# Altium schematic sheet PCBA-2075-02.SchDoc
size Tabloid; Organization: Hebi Robotics; Address1: Suite 780; Address2: 5001 Baum Blvd; Address3: Pittsburgh, PA 15213; Address4: USA
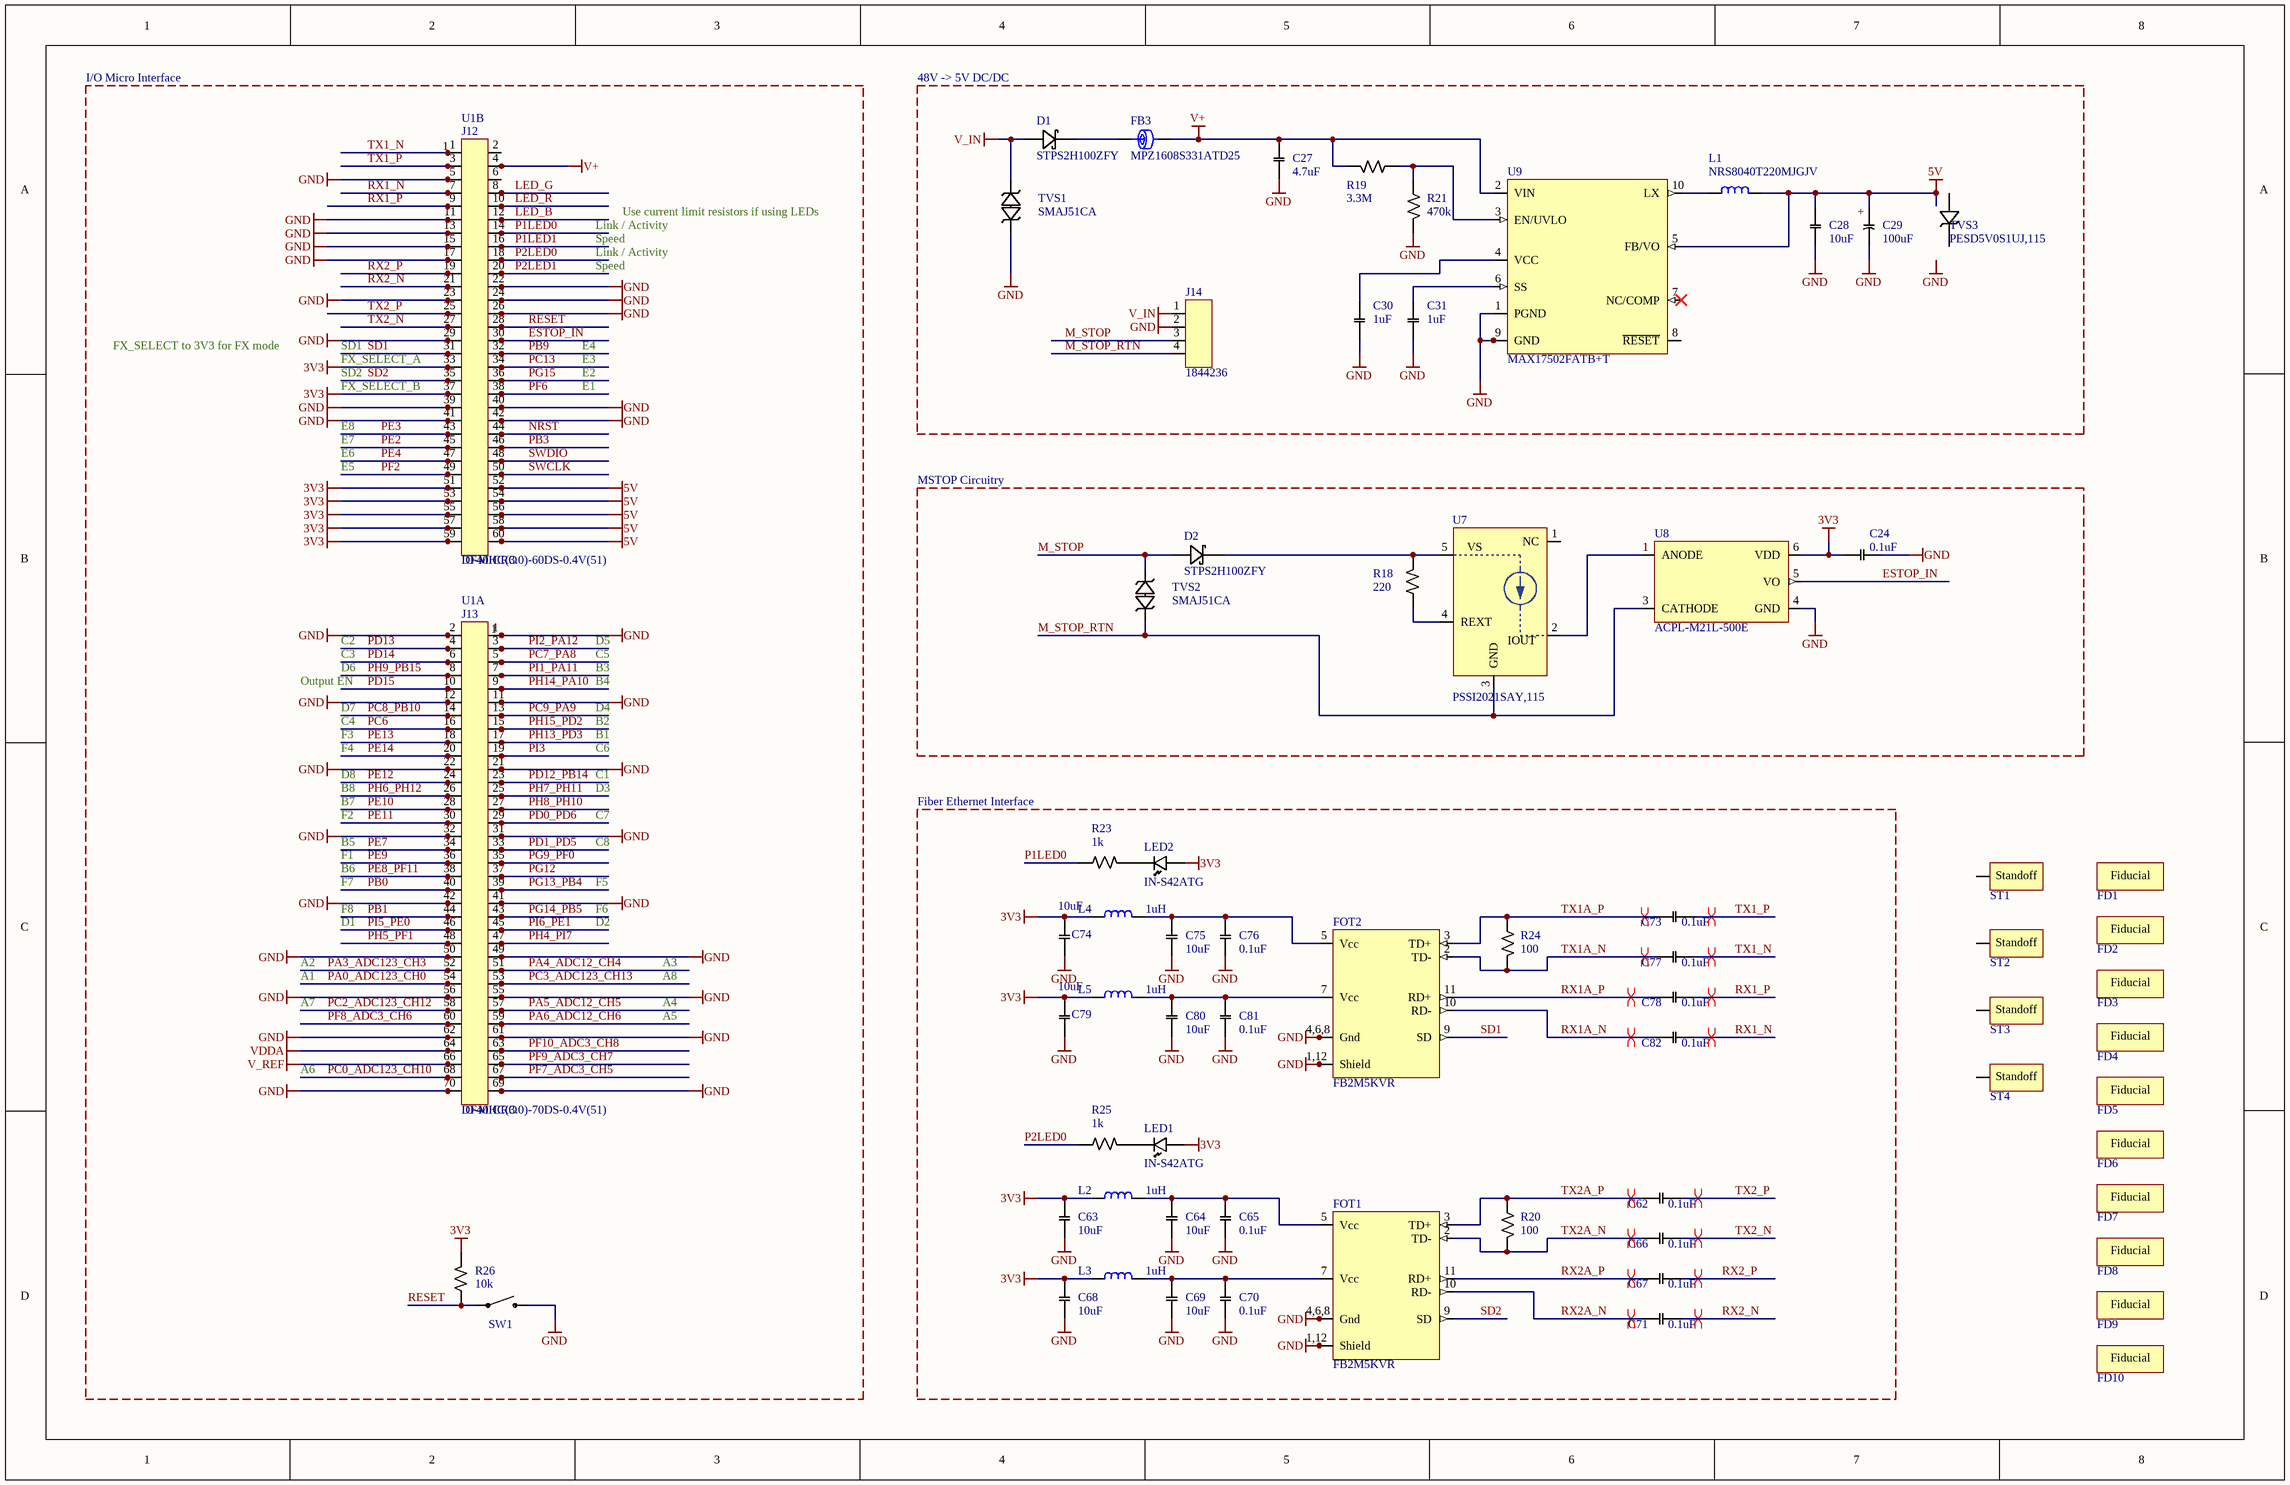
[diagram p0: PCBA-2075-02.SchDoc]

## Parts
C24  Capacitance: 0.1uF  [C0402]  (hidden comment: CMP-00040-11)
C27  Capacitance: 4.7uF  [C1210]  (hidden comment: C-4.7uf-X7S-100V-20%-1210)
C28  Capacitance: 10uF  [C0603]  (hidden comment: C-10uf-X5R-16V-10%-0603)
C29  Capacitance: 100uF  [CAPAE127P600-8N]  (hidden comment: 16SVPC100M)
C30  Capacitance: 1uF  [C0603]  (hidden comment: C-1uf-X7R-25V-10%-0603)
C31  Capacitance: 1uF  [C0603]  (hidden comment: C-1uf-X7R-25V-10%-0603)
C62  Capacitance: 0.1uF  [C0402]  (hidden comment: CMP-00040-11)
C63  Capacitance: 10uF  [C0603]  (hidden comment: C-10uf-X5R-16V-10%-0603)
C64  Capacitance: 10uF  [C0603]  (hidden comment: C-10uf-X5R-16V-10%-0603)
C65  Capacitance: 0.1uF  [C0402]  (hidden comment: CMP-00040-11)
C66  Capacitance: 0.1uF  [C0402]  (hidden comment: CMP-00040-11)
C67  Capacitance: 0.1uF  [C0402]  (hidden comment: CMP-00040-11)
C68  Capacitance: 10uF  [C0603]  (hidden comment: C-10uf-X5R-16V-10%-0603)
C69  Capacitance: 10uF  [C0603]  (hidden comment: C-10uf-X5R-16V-10%-0603)
C70  Capacitance: 0.1uF  [C0402]  (hidden comment: CMP-00040-11)
C71  Capacitance: 0.1uF  [C0402]  (hidden comment: CMP-00040-11)
C73  Capacitance: 0.1uF  [C0402]  (hidden comment: CMP-00040-11)
C74  Capacitance: 10uF  [C0603]  (hidden comment: C-10uf-X5R-16V-10%-0603)
C75  Capacitance: 10uF  [C0603]  (hidden comment: C-10uf-X5R-16V-10%-0603)
C76  Capacitance: 0.1uF  [C0402]  (hidden comment: CMP-00040-11)
C77  Capacitance: 0.1uF  [C0402]  (hidden comment: CMP-00040-11)
C78  Capacitance: 0.1uF  [C0402]  (hidden comment: CMP-00040-11)
C79  Capacitance: 10uF  [C0603]  (hidden comment: C-10uf-X5R-16V-10%-0603)
C80  Capacitance: 10uF  [C0603]  (hidden comment: C-10uf-X5R-16V-10%-0603)
C81  Capacitance: 0.1uF  [C0402]  (hidden comment: CMP-00040-11)
C82  Capacitance: 0.1uF  [C0402]  (hidden comment: CMP-00040-11)
D1  STPS2H100ZFY  [SOD123F_ST]
D2  STPS2H100ZFY  [SOD123F_ST]
FB3  MPZ1608S331ATD25  [FB0603]
FD1  FIDUCIAL  [fiducial_01]  (value not drawn)  (no BOM)
FD2  FIDUCIAL  [fiducial_01]  (value not drawn)  (no BOM)
FD3  FIDUCIAL  [fiducial_01]  (value not drawn)  (no BOM)
FD4  FIDUCIAL  [fiducial_01]  (value not drawn)  (no BOM)
FD5  *  [fiducial_01_no_overlay]  (value not drawn)  (no BOM)
FD6  *  [fiducial_01_no_overlay]  (value not drawn)  (no BOM)
FD7  *  [fiducial_01_no_overlay]  (value not drawn)  (no BOM)
FD8  *  [fiducial_01_no_overlay]  (value not drawn)  (no BOM)
FD9  *  [fiducial_01_no_overlay]  (value not drawn)  (no BOM)
FD10  *  [fiducial_01_no_overlay]  (value not drawn)  (no BOM)
FOT1  FB2M5KVR  [OPTOLOCK]
FOT2  FB2M5KVR  [OPTOLOCK]
J12  DF40HC(3.0)-60DS-0.4V(51)  [DF40HC(3.0)-60DS-0.4V(51)]
J13  DF40HC(3.0)-70DS-0.4V(51)  [DF40HC(3.0)-70DS-0.4V(51)]
J14  1844236  [1844236]
L1  NRS8040T220MJGJV  [NR8040T220M]
L2  Inductance: 1uH  [I0603]  (hidden comment: ASMPH-0603-1R0M-T)
L3  Inductance: 1uH  [I0603]  (hidden comment: ASMPH-0603-1R0M-T)
L4  Inductance: 1uH  [I0603]  (hidden comment: ASMPH-0603-1R0M-T)
L5  Inductance: 1uH  [I0603]  (hidden comment: ASMPH-0603-1R0M-T)
LED1  IN-S42ATG  [IN-S42AT]
LED2  IN-S42ATG  [IN-S42AT]
R18  Resistance: 220  [R0603]  (hidden comment: R-220-1%-0.25w-0603)
R19  Resistance: 3.3M  [R0402]  (hidden comment: R-3.3M-1%-0.063w-0402)
R20  value 100  [R0402]  (hidden comment: R-100-1%-0.063w-0402)
R21  Resistance: 470k  [R0402]  (hidden comment: R-470k-1%-0.063w-0402)
R23  Resistance: 1k  [R0402]  (hidden comment: R-1k-1%-0.063w-0402)
R24  value 100  [R0402]  (hidden comment: R-100-1%-0.063w-0402)
R25  Resistance: 1k  [R0402]  (hidden comment: R-1k-1%-0.063w-0402)
R26  Resistance: 10k  [R0402]  (hidden comment: R-10k-1%-0.063w-0402)
ST1  9774030960R  [9774030960R]  (value not drawn)
ST2  9774030960R  [9774030960R]  (value not drawn)
ST3  9774030960R  [9774030960R]  (value not drawn)
ST4  9774030960R  [9774030960R]  (value not drawn)
SW1  222ADVBA  [222ADVBA]  (value not drawn)
TVS1  SMAJ51CA  [SMA_BI_BOURNS]
TVS2  SMAJ51CA  [SMA_BI_BOURNS]
TVS3  PESD5V0S1UJ,115  [SOD-323F_NXP]
U1  IO-MICRO  [IO-MICRO-Footprint-1]  (parts A,B of 2)  (no BOM)
U7  PSSI2021SAY,115  [PSSI2021SAY,115]
U8  ACPL-M21L-500E  [SOT125P700X260-5N]
U9  MAX17502FATB+T  [10_TDFN_MAXIM]

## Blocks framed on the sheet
48V -> 5V DC/DC: C27-C31 D1 FB3 J14 L1 R19 R21 TVS1 TVS3 U9
MSTOP Circuitry: C24 D2 R18 TVS2 U7 U8
Fiber Ethernet Interface: C62-C71 C73-C82 FOT1 FOT2 L2-L5 LED1 LED2 R20 R23-R25

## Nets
3V3: C24.1 C63.2 C68.2 C74.2 C79.2 J12.33 J12.37 J12.51 J12.53 J12.55 J12.57 J12.59 L2.1 L3.1 L4.1 L5.1 LED1.A LED2.A R26.2 U1.B33 U1.B37 U1.B51 U1.B53 U1.B55 U1.B57 U1.B59 U8.6(VDD)
5V: C28.2 C29.+ J12.52 J12.54 J12.56 J12.58 J12.60 L1.2 U1.B52 U1.B54 U1.B56 U1.B58 U1.B60 U9.5(FB/VO)
GND: C24.2 C27.1 C28.1 C29.- C30.2 C31.2 C63.1 C64.1 C65.1 C68.1 C69.1 C70.2 C74.1 C75.1 C76.1 C79.1 C80.1 C81.2 FOT1.1(Shield) FOT1.4(Gnd) FOT1.6(Gnd) FOT1.8(Gnd) FOT1.12(Shield) FOT2.1(Shield) FOT2.4(Gnd) FOT2.6(Gnd) FOT2.8(Gnd) FOT2.12(Shield) J12.5 J12.11 J12.13 J12.15 J12.17 J12.22 J12.23 J12.24 J12.26 J12.29 J12.39 J12.40 J12.41 J12.42 J13.1 J13.2 J13.11 J13.12 J13.21 J13.22 J13.31 J13.32 J13.41 J13.42 J13.49 J13.50 J13.55 J13.56 J13.61 J13.62 J13.69 J13.70 J14.2 R21.2 SW1.2 TVS1.A U1.A1 U1.A2 U1.A11 U1.A12 U1.A21 U1.A22 U1.A31 U1.A32 U1.A41 U1.A42 U1.A49 U1.A50 U1.A55 U1.A56 U1.A61 U1.A62 U1.A69 U1.A70 U1.B5 U1.B11 U1.B13 U1.B15 U1.B17 U1.B22 U1.B23 U1.B24 U1.B26 U1.B29 U1.B39 U1.B40 U1.B41 U1.B42 U8.4(GND) U9.1(PGND) U9.9(GND) U9.11(GND)
V+: C27.2 FB3.2 J12.4 R19.2 U1.B4 U9.2(VIN)
V_IN: D1.A J14.1 TVS1.C
V_REF: J13.66 U1.A66
VDDA: J13.64 U1.A64
ESTOP_IN: J12.30 U1.B30 U8.5(VO)
LED_B: J12.12 U1.B12
LED_G: J12.8 U1.B8
LED_R: J12.10 U1.B10
M_STOP: D2.A J14.3 TVS2.C
M_STOP_RTN: J14.4 TVS2.A U7.3(GND) U8.3(CATHODE)
NRST: J12.44 U1.B44
P1LED0: J12.14 R23.1 U1.B14
P1LED1: J12.16 U1.B16
P2LED0: J12.18 R25.1 U1.B18
P2LED1: J12.20 U1.B20
PA0_ADC123_CH0: J13.54 U1.A54
PA3_ADC123_CH3: J13.52 U1.A52
PA4_ADC12_CH4: J13.51 U1.A51
PA5_ADC12_CH5: J13.57 U1.A57
PA6_ADC12_CH6: J13.59 U1.A59
PB0: J13.40 U1.A40
PB1: J13.44 U1.A44
PB3: J12.46 U1.B46
PB9: J12.32 U1.B32
PC0_ADC123_CH10: J13.68 U1.A68
PC2_ADC123_CH12: J13.58 U1.A58
PC3_ADC123_CH13: J13.53 U1.A53
PC6: J13.16 U1.A16
PC7_PA8: J13.5 U1.A5
PC8_PB10: J13.14 U1.A14
PC9_PA9: J13.13 U1.A13
PC13: J12.34 U1.B34
PD0_PD6: J13.29 U1.A29
PD1_PD5: J13.33 U1.A33
PD12_PB14: J13.23 U1.A23
PD13: J13.4 U1.A4
PD14: J13.6 U1.A6
PD15: J13.10 U1.A10
PE2: J12.45 U1.B45
PE3: J12.43 U1.B43
PE4: J12.47 U1.B47
PE7: J13.34 U1.A34
PE8_PF11: J13.38 U1.A38
PE9: J13.36 U1.A36
PE10: J13.28 U1.A28
PE11: J13.30 U1.A30
PE12: J13.24 U1.A24
PE13: J13.18 U1.A18
PE14: J13.20 U1.A20
PF2: J12.49 U1.B49
PF6: J12.38 U1.B38
PF7_ADC3_CH5: J13.67 U1.A67
PF8_ADC3_CH6: J13.60 U1.A60
PF9_ADC3_CH7: J13.65 U1.A65
PF10_ADC3_CH8: J13.63 U1.A63
PG9_PF0: J13.35 U1.A35
PG12: J13.37 U1.A37
PG13_PB4: J13.39 U1.A39
PG14_PB5: J13.43 U1.A43
PG15: J12.36 U1.B36
PH4_PI7: J13.47 U1.A47
PH5_PF1: J13.48 U1.A48
PH6_PH12: J13.26 U1.A26
PH7_PH11: J13.25 U1.A25
PH8_PH10: J13.27 U1.A27
PH9_PB15: J13.8 U1.A8
PH13_PD3: J13.17 U1.A17
PH14_PA10: J13.9 U1.A9
PH15_PD2: J13.15 U1.A15
PI1_PA11: J13.7 U1.A7
PI2_PA12: J13.3 U1.A3
PI3: J13.19 U1.A19
PI5_PE0: J13.46 U1.A46
PI6_PE1: J13.45 U1.A45
RESET: J12.28 R26.1 SW1.1 U1.B28
RX1_N: C82.2 J12.7 U1.B7
RX1_P: C78.2 J12.9 U1.B9
RX1A_N: C82.1 FOT2.10(RD-)
RX1A_P: C78.1 FOT2.11(RD+)
RX2_N: C71.1 J12.21 U1.B21
RX2_P: C67.1 J12.19 U1.B19
RX2A_N: C71.2 FOT1.10(RD-)
RX2A_P: C67.2 FOT1.11(RD+)
SD1: FOT2.9(SD) J12.31 U1.B31
SD2: FOT1.9(SD) J12.35 U1.B35
SWCLK: J12.50 U1.B50
SWDIO: J12.48 U1.B48
TX1_N: C77.2 J12.1 U1.B1
TX1_P: C73.2 J12.3 U1.B3
TX1A_N: C77.1 FOT2.2(TD-) R24.2
TX1A_P: C73.1 FOT2.3(TD+) R24.1
TX2_N: C66.1 J12.27 U1.B27
TX2_P: C62.1 J12.25 U1.B25
TX2A_N: C66.2 FOT1.2(TD-) R20.2
TX2A_P: C62.2 FOT1.3(TD+) R20.1
NetC30_1: C30.1 U9.4(VCC)
NetC31_1: C31.1 U9.6(SS)
NetC64_2: C64.2 C65.2 FOT1.5(Vcc) L2.2
NetC69_2: C69.2 C70.1 FOT1.7(Vcc) L3.2
NetC75_2: C75.2 C76.2 FOT2.5(Vcc) L4.2
NetC80_2: C80.2 C81.1 FOT2.7(Vcc) L5.2
NetD1_C: D1.C FB3.1
NetD2_C: D2.C R18.2 U7.5(VS)
NetJ12_2: J12.2 U1.B2
NetJ12_6: J12.6 U1.B6
NetL1_1: L1.1 U9.10(LX)
NetLED1_C: LED1.C R25.2
NetLED2_C: LED2.C R23.2
NetR18_1: R18.1 U7.4(REXT)
NetR19_1: R19.1 R21.1 U9.3(EN/UVLO)
NetU7_2: U7.2(IOUT) U8.1(ANODE)

Not connected (* = marked no-connect by the designer): ST1 1; ST2 1; ST3 1; ST4 1; TVS3 A C; U7 1(NC); U9 7(NC/COMP)* 8(~{RESET})

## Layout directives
differential pair: RX1_N, RX1_P, RX1A_N, RX1A_P, RX2_N, RX2_P, RX2A_N, RX2A_P, TX1_N, TX1_P, TX1A_N, TX1A_P, TX2_N, TX2_P, TX2A_N, TX2A_P

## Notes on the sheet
- I/O Micro Interface
- Link / Activity
- Use current limit resistors if using LEDs
- Speed
- FX_SELECT to 3V3 for FX mode
- SD1
- FX_SELECT_A
- E3
- E4
- SD2
- FX_SELECT_B
- E8
- E1
- E2
- E5
- E6
- E7
- Output EN
- C2
- C3
- D6
- B3
- B4
- C5
- D5
- C4
- D7
- F4
- F3
- B1
- B2
- C6
- D4
- B7
- B8
- D8
- F2
- C1
- C7
- D3
- B5
- B6
- F7
- F1
- C8
- F5
- A2
- D1
- F8
- D2
- F6
- A3
- A1
- A7
- A4
- A5
- A8
- A6
- Labels drawn without touching a wire or pin: GND

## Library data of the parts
C24 C62 C65-C67 C70 C71 C73 C76-C78 C81 C82 = CMP-00040-11: Capacitor Ceramic 0.1uF 25V X7R 10% SMD 0402
C27 = C-4.7uf-X7S-100V-20%-1210-6: Capacitor Ceramic 4.7uF 100V X7S 20% SMD 1210
C28 C63 C64 C68 C69 C74 C75 C79 C80 = CMP-00102-2: Capacitor Ceramic 10uF 16V X5R 10% SMD 0603
C29 = CMP-00071-2: CAP ALUM POLY 100UF 20% 16V SMD; Ripple Current: 2.49A; Dissipation Factor: 12%; ESR (Equivalent Series Resistance): 24mR; Leakage Current: 300uA; Life (Hours): 2000Hour; Polarity: Polar
C30 C31 = CMP-00057-3: Capacitor Ceramic 1uF 25V X7R 10% SMD 0603
D1 D2 = CMP-698-0009-4: DIODE SCHOTTKY 100V 2A SOD123F; Voltage - Forward (Vf) (Max) @ If: 960mV @ 4A; Speed: Fast Recovery =< 500ns, > 200mA (Io); Current - Reverse Leakage @ Vr: 1µA @ 100V
FB3 = CMP-00231-5: FERRITE CHIP 330 OHM 1.7A 0603; DC Resistance (DCR): 80 mOhm Max
FD1-FD4 = fiducial_01
FD5-FD10 = fiducial_01_no_overlay: Fiducial with no overlay
FOT1 FOT2 = CMP-1167-0000-7: Industrial Ethernet Fiber Optic; Manufacturer: Firecomms; Data Rate: 250Mbps; Wavelength: 650nm; Voltage - Supply: 3.3V
J12 = CMP-00492-3: CONN RCPT 60POS 0.4MM SMD GOLD; Connector Type: Receptacle; Mated Stacking Heights: 3mm; Number of Contacts: 60; Pitch: 0.016inch
J13 = CMP-00491-1: CONN RCPT 70POS 0.4MM SMD GOLD; Manufacturer: Hirose
J14 = CMP-1158-0000-1: HEADER TERM BLOCK 3.5MM 4POS; Manufacturer: Phoenix Contact
L1 = CMP-00359-2: FIXED IND 22UH 2.2A 85.8 MOHM; Type: Wirewound; Tolerance: ±20%; Shielding: Shielded; DC Resistance (DCR): 85.8 mOhm Max; Material - Core: Ferrite
L2-L5 = CMP-00368-3: FIXED IND 1UH 1A 200 MOHM SMD; DC Resistance (DCR): 200mR; Tolerance: 20%; Shielding: Shielded; Case/Size Code: 0603; Core Material: Ferrite; Inductor Application: POWER INDUCTOR; Inductor Type: GENERAL PURPOSE INDUCTOR; Number of Functions: 1; Number of Terminals/Pins: 2; Self Resonant Frequency: 125MHz; Shape/Size Description: RECTANGULAR PACKAGE; Test Frequency: 1MHz
LED1 LED2 = CMP-00249-2: LED GREEN CLEAR 0402 SMD; Dominant Wavelength: 525nm; Forward Voltage: 3.3V; Lens Size: 0.45mm; Lens Style: Flat; Luminous Intensity: 450mcd; Test Current: 20mA; Viewing Angle: 130°
R18 = CMP-00175-3: Resistor 0603 220 Ohm 1% 1-4 Watt; Power: 0.25W, 1/4W
R19 = CMP-00141-5: Resistor 0402 3.3M Ohm 1% 1-16 Watt; Power: 0.063W, 1/16W
R20 R24 = CMP-00022-6: Resistor 0402 100 Ohm 1% 1-16 Watt; Power: 0.063W, 1/16W
R21 = CMP-00804-1: Resistor 0402 470k Ohm 1% 1-16 Watt; Power: 0.063W, 1/16W
R23 R25 = CMP-00012-5: Resistor 0402 1k Ohm 1% 1-16 Watt; Power: 0.063W, 1/16W
R26 = CMP-00015-10: Resistor 0402 10k Ohm 1% 1-16 Watt; Power: 0.063W, 1/16W
ST1-ST4 = CMP-504-0002-4: ROUND SPACER M3.3 STEEL 3MM; Manufacturer: Wurth Electronics Inc; Threaded/Unthreaded: Unthreaded; Between Board Height: 0.118" (3.00mm); Plating: Tin
SW1 = CMP-00538-1: Tactile Switch SPST-NO Top Actuated Through Hole; Manufacturer: CTS; Switch Function: Off-Mom; Actuator Type: Standard; Operating Force: 160gf; Switch Travel: 0.25mm; Mechanical Life: 1000000Cycles; Throw Configuration: SPST; Illumination Type: Non-Illuminated
TVS1 TVS2 = CMP-00457-4: TVS DIODE 51VWM 82.4VC DO214AC; Voltage - Reverse Standoff (Typ): 51V; Voltage - Breakdown (Min): 56.7V; Voltage - Clamping (Max) @ Ipp: 82.4V; Current - Peak Pulse (10/1000µs): 4.9A; Power - Peak Pulse: 400W; Power Line Protection: No; Bidirectional Channels: 1
TVS3 = CMP-00446-3: TVS DIODE 5VWM 19VC SOD323F; Unidirectional Channels: 1; Voltage - Reverse Standoff (Typ): 5V (Max); Voltage - Breakdown (Min): 6.2V; Voltage - Clamping (Max) @ Ipp: 19V; Current - Peak Pulse (10/1000µs): 47A (8/20µs); Power - Peak Pulse: 890W; Power Line Protection: No; Capacitance @ Frequency: 480pF @ 1MHz
U1 = CMP-00789-8: IO Micro Composite Component
U7 = CMP-631-0001-3: Current Source Regulator  50mA 5-TSSOP; Input Current: 240uA; Max Power Dissipation: 335mW; Max Supply Voltage: 75V; Polarity: PNP
U8 = CMP-636-0002-3: OPTOISO 3.75KV PUSH PULL 5SO; Number of Channels: 1; Input Type: DC; Output Type: PUSH-PULL; Direction: Unidirectional; Fall Time: 11ns; Forward Current: 2.2mA; Forward Voltage: 1.5V; Input Current: 6mA; Max Input Current: 8mA; Max Output Current: 10mA; Max Power Dissipation: 600mW; Propagation Delay: 250ns; Reverse Breakdown Voltage: 5V
U9 = CMP-452-0001-3: IC REG BUCK 5V 1A SYNC 10TDFN; Manufacturer: Maxim Integrated; Output Type: Fixed; Number of Outputs: 1; Frequency - Switching: 600kHz; Synchronous Rectifier: Yes; Function: Step-Down; Output Configuration: Positive; Voltage - Input (Min): 4.5V; Voltage - Input (Max): 60V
